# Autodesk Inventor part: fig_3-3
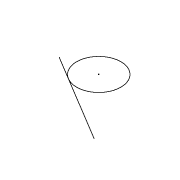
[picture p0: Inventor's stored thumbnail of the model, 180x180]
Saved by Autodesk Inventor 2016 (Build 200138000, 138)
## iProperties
Created: 2009-11
Part Number: fig_3-3
Document SubType Name: Modeling
Designer: Sham
Density: 1 g/cm^3
Material: Generic
Appearance: Default
Author: Sham
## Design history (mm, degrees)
sketch "Sketch1"
  geometry: L1 (-21, -10.296)-(20, -35); C1 r 10.296 at (-4.831, -8.018)
  constraints: 2 end point, 1 centre point, 1 tangent, 1 other
